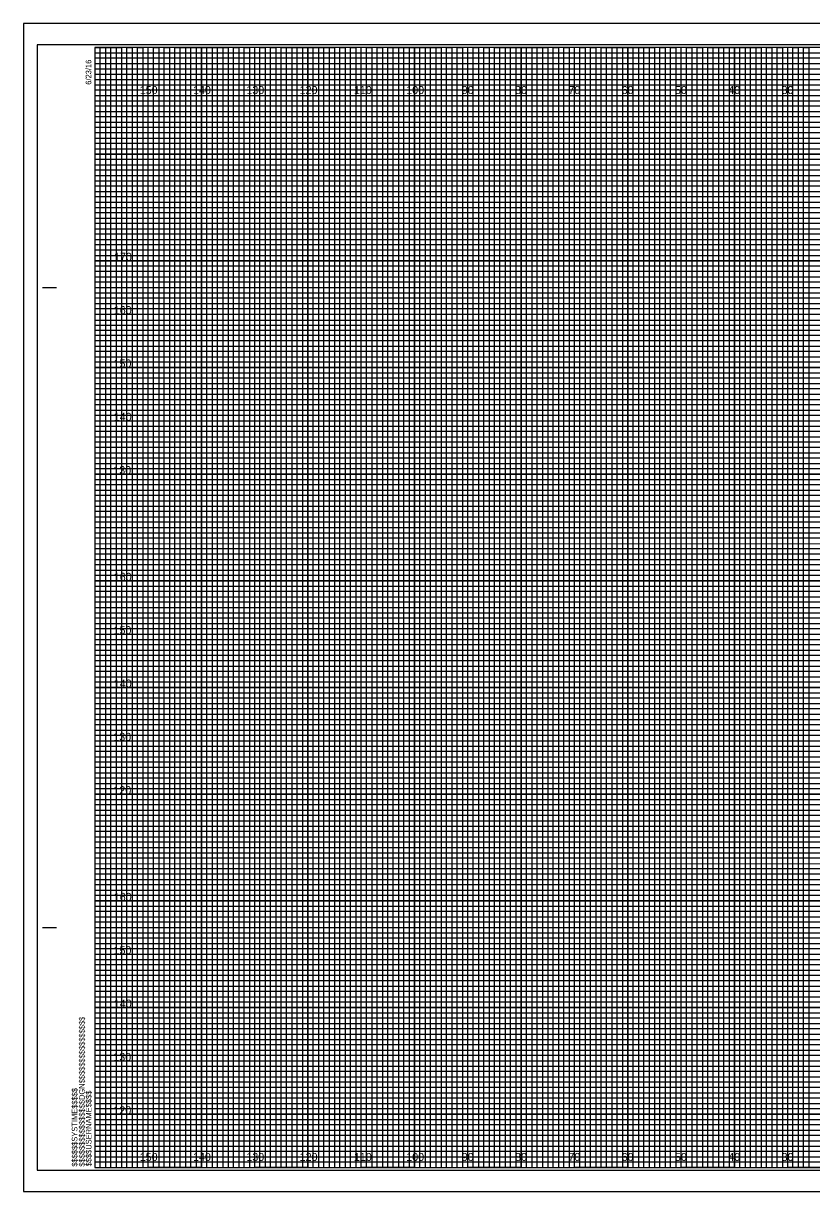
# Model space of a CAD drawing. Extents: x -13 to 323, y -5 to 1094.
# Drawn here: x -13.4 to 134.5, y 875.5 to 1094.5 of the extents above; entities that cross this region are included whole.
import ezdxf

# ---------------------------------------------------------------- set-up
doc = ezdxf.new("R2010")
doc.units = 0
for name, color, linetype in [('Exist Cross Section Cell', 7, 'Continuous'), ('Exist XS Center Line Elevation Label', 7, 'Continuous'), ('Exist XS Ground Line', 7, 'Continuous'), ('Prop CMT Pvmt Course 1', 7, 'Continuous'), ('Prop CMT Pvmt Course 3', 7, 'Continuous'), ('Prop CMT Pvmt Surface', 7, 'Continuous'), ('Prop CMT Pvmt Surface Shoulder', 7, 'Continuous'), ('Prop CMT Shld Paved Course 1', 7, 'Continuous'), ('Prop CMT Shld Paved Course 2', 7, 'Continuous'), ('Prop CMT Shld Paved Course 3', 7, 'Continuous'), ('Prop CMT Subgrade Earthwork', 7, 'Continuous')]:
    doc.layers.add(name, color=color, linetype=linetype)

msp = doc.modelspace()

# ---------------------------------------------------------------- linework, layer by layer
at = {"layer": 'Exist XS Center Line Elevation Label'}
for points in [[(0, 1090), (5, 1090), (5, 880), (15, 880), (15, 1090), (25, 1090), (25, 880), (35, 880), (35, 1090), (45, 1090), (45, 880), (55, 880), (55, 1090), (65, 1090), (65, 880), (75, 880), (75, 1090), (85, 1090), (85, 880), (95, 880), (95, 1090), (105, 1090), (105, 880), (115, 880), (115, 1090), (125, 1090), (125, 880), (135, 880)], [(0, 1085), (275, 1085)], [(0, 1065), (320, 1065), (320, 1075), (0, 1075)], [(0, 1045), (320, 1045), (320, 1055), (0, 1055)], [(0, 1025), (320, 1025), (320, 1035), (0, 1035)], [(0, 1005), (320, 1005), (320, 1015), (0, 1015)], [(0, 985), (320, 985), (320, 995), (0, 995)], [(0, 965), (320, 965), (320, 975), (0, 975)], [(0, 945), (320, 945), (320, 955), (0, 955)], [(0, 925), (320, 925), (320, 935), (0, 935)], [(0, 905), (320, 905), (320, 915), (0, 915)], [(0, 885), (320, 885), (320, 895), (0, 895)]]:
    msp.add_lwpolyline(points, dxfattribs=at)
at = {"layer": 'Exist XS Ground Line'}
for p, q in [((10, 1090), (0, 1090)), ((10, 880), (10, 1090)), ((30, 1090), (20, 1090)), ((20, 1090), (20, 880)), ((30, 880), (30, 1090)), ((50, 1090), (40, 1090)), ((40, 1090), (40, 880)), ((50, 880), (50, 1090)), ((70, 1090), (60, 1090)), ((60, 1090), (60, 880)), ((70, 880), (70, 1090)), ((90, 1090), (80, 1090)), ((80, 1090), (80, 880)), ((90, 880), (90, 1090)), ((110, 1090), (100, 1090)), ((100, 1090), (100, 880)), ((110, 880), (110, 1090)), ((130, 1090), (120, 1090)), ((120, 1090), (120, 880)), ((130, 880), (130, 1090)), ((20, 880), (10, 880)), ((40, 880), (30, 880)), ((60, 880), (50, 880)), ((80, 880), (70, 880)), ((100, 880), (90, 880)), ((120, 880), (110, 880)), ((140, 880), (130, 880))]:
    msp.add_line(p, q, dxfattribs=at)
for points in [[(0, 1080), (320, 1080), (320, 1070), (0, 1070)], [(0, 1060), (320, 1060), (320, 1050), (0, 1050)], [(0, 1040), (320, 1040), (320, 1030), (0, 1030)], [(0, 1020), (320, 1020), (320, 1010), (0, 1010)], [(0, 1000), (320, 1000), (320, 990), (0, 990)], [(0, 980), (320, 980), (320, 970), (0, 970)], [(0, 960), (320, 960), (320, 950), (0, 950)], [(0, 940), (320, 940), (320, 930), (0, 930)], [(0, 920), (320, 920), (320, 910), (0, 910)], [(0, 900), (320, 900), (320, 890), (0, 890)]]:
    msp.add_lwpolyline(points, dxfattribs=at)
at = {"layer": 'Prop CMT Pvmt Course 3'}
msp.add_lwpolyline([(-13.4, 875.5), (323.3, 875.5), (323.3, 1094.5), (-13.4, 1094.5)], close=True, dxfattribs=at)
at = {"layer": 'Prop CMT Pvmt Surface'}
for p, q in [((10, 880), (10, 1090)), ((20, 880), (20, 1090)), ((30, 880), (30, 1090)), ((40, 880), (40, 1090)), ((50, 880), (50, 1090)), ((60, 880), (60, 1090)), ((70, 880), (70, 1090)), ((80, 880), (80, 1090)), ((90, 880), (90, 1090)), ((100, 880), (100, 1090)), ((110, 880), (110, 1090)), ((120, 880), (120, 1090)), ((130, 880), (130, 1090)), ((0, 1080), (320, 1080)), ((0, 1070), (320, 1070)), ((0, 1060), (320, 1060)), ((0, 1050), (320, 1050)), ((0, 1040), (320, 1040)), ((0, 1030), (320, 1030)), ((0, 1020), (320, 1020)), ((0, 1010), (320, 1010)), ((0, 1000), (320, 1000)), ((0, 990), (320, 990)), ((0, 980), (320, 980)), ((0, 970), (320, 970)), ((0, 960), (320, 960)), ((0, 950), (320, 950)), ((0, 940), (320, 940)), ((0, 930), (320, 930)), ((0, 920), (320, 920)), ((0, 910), (320, 910)), ((0, 900), (320, 900)), ((0, 890), (320, 890))]:
    msp.add_line(p, q, dxfattribs=at)
at = {"layer": 'Prop CMT Pvmt Surface Shoulder'}
for p, q in [((323.3, 1094.5), (-13.4, 1094.5)), ((-13.4, 1094.5), (-13.4, 875.5)), ((-13.4, 875.5), (323.3, 875.5))]:
    msp.add_line(p, q, dxfattribs=at)
at = {"layer": 'Prop CMT Shld Paved Course 1'}
for p, q in [((0, 1089), (260, 1089)), ((260, 1087.98), (0, 1087.98)), ((0, 1087.98), (0, 1087)), ((0, 1087), (260, 1087)), ((260, 1085.89), (0, 1085.89)), ((0, 1085.89), (0, 1084)), ((0, 1084), (320, 1084))]:
    msp.add_line(p, q, dxfattribs=at)
for points in [[(0, 1083), (270, 1083), (320, 1083), (320, 1082), (0, 1082)], [(0, 1081), (320, 1081), (320, 1079), (0, 1079)], [(0, 1078), (320, 1078), (320, 1077), (0, 1076.98)], [(0, 1076), (320, 1076), (320, 1074), (0, 1074)], [(0, 1073), (320, 1073), (320, 1072), (0, 1072)], [(0, 1071), (320, 1071), (320, 1069), (0, 1069)], [(0, 1068), (320, 1068), (320, 1067), (0, 1067)], [(0, 1066), (320, 1066), (320, 1064), (0, 1064)], [(0, 1063), (320, 1063), (320, 1062), (0, 1062)], [(0, 1061), (320, 1061), (320, 1059), (0, 1059)], [(0, 1058), (320, 1058), (320, 1057), (0, 1057)], [(0, 1056), (320, 1056), (320, 1053.95), (320, 1053), (320, 1052), (0, 1052)], [(0, 1054), (320, 1054), (320, 1053), (0, 1053)], [(0, 1051), (320, 1051), (320, 1049), (0, 1049.03)], [(0, 1049.03), (320, 1049), (320, 1048), (0, 1048)], [(0, 1047), (320, 1047), (320, 1046), (0, 1046)], [(0, 1044), (320, 1044), (320, 1043), (0, 1043)], [(0, 1042), (320, 1042), (320, 1041), (0, 1041)], [(-0.07, 1038.89), (320, 1038.89), (320, 1037.88), (-0.07, 1037.88)], [(0, 1037), (320, 1037), (320, 1036), (0, 1036)], [(0, 1034), (320, 1034), (320, 1033), (0, 1033)], [(0, 1032), (320, 1032), (320, 1031), (0, 1031)], [(0, 1029), (320, 1029), (320, 1028), (0, 1028)], [(0, 1027), (320, 1027), (320, 1026), (0, 1026)], [(0, 1024), (320, 1024), (320, 1023), (0, 1023)], [(0, 1022), (320, 1022), (320, 1021), (0, 1021)], [(0, 1019), (320, 1019), (319.99, 1017.98), (0, 1018)], [(0, 1017), (320, 1017), (320, 1016), (0, 1016)], [(0, 1014), (320, 1014), (320, 1013), (0, 1013)], [(0, 1012), (320, 1012), (320, 1011), (0, 1011)], [(0, 1009), (320, 1009), (320, 1008), (0, 1008)], [(0, 1007), (320, 1007), (320, 1006), (0, 1006)], [(0, 1004), (320, 1004), (320, 1003), (0, 1003)], [(0, 1002), (320, 1002), (320, 1001), (0, 1001)], [(0, 999), (320, 999), (320, 998), (0, 998)], [(0, 996.99), (320.07, 996.91), (320, 996), (0, 996)], [(0, 994), (320, 994), (320, 993), (0, 993)], [(0, 992), (320, 992), (320, 991), (0, 991)], [(0, 989), (320, 989), (320, 988), (0, 988)], [(0, 987), (320, 987), (320, 986), (0, 986)], [(0, 984), (320, 984), (320, 983), (0, 983)], [(0, 982), (320, 982), (320, 981), (0, 981)], [(0, 979), (320, 979), (320, 978), (0, 978)], [(0, 977), (320, 977), (320, 976), (0, 976)], [(0, 974), (320, 974), (320, 973), (0, 973)], [(0, 972), (320, 972), (320, 971), (0, 971)], [(0, 969), (320, 969), (320, 968), (0, 968)], [(0, 967), (320, 967), (320, 966), (0, 966)], [(0, 964), (320, 964), (320, 963), (0, 963)], [(0, 962), (320, 962), (320, 961), (0, 961)], [(0, 959), (320, 959), (319.99, 957.98), (0, 958)], [(0, 957), (320, 957), (320, 956), (0, 956)], [(0, 954), (320, 954), (320, 953), (0, 953)], [(0, 952), (320, 952), (320, 951), (0, 951)], [(0, 949), (320, 949), (320, 948), (0, 948)], [(0, 947), (320, 947), (320, 946), (0, 946)], [(0, 944), (320, 944), (320, 943), (0, 943)], [(0, 942), (320, 942), (320, 941), (0, 941)], [(0, 939), (320, 939), (320, 938), (0, 938)], [(0, 936.99), (320.07, 936.91), (320, 936), (0, 936)], [(0, 934), (320, 934), (320, 933), (0, 933)], [(0, 932), (320, 932), (320, 931), (0, 931)], [(0, 929), (320, 929), (320, 928), (0, 928)], [(0, 927), (320, 927), (320, 926), (0, 926)], [(0, 924), (320, 924), (320, 923), (0, 923)], [(0, 922), (320, 922), (320, 921), (0, 921)], [(0, 919), (320, 919), (320, 918), (0, 918)], [(0, 917), (320, 917), (320, 916), (0, 916)], [(0, 914), (320, 914), (320, 913), (0, 913)], [(0, 912), (320, 912), (320, 911), (0, 911)], [(0, 909), (320, 909), (320, 908), (0, 908)], [(0, 907), (320, 907), (320, 906), (0, 906)], [(0, 904), (320, 904), (320, 903), (0, 903)], [(0, 902), (320, 902), (320, 901), (0, 901)], [(0, 899), (320, 899), (320, 898), (0, 898)], [(0, 897), (320, 897), (320, 896), (0, 896)], [(0, 894), (320, 894), (320, 893), (0, 893)], [(0, 892), (320, 892), (320, 891), (0, 891)], [(0, 889), (320, 889), (320, 888), (0, 888)], [(0, 887), (320, 887), (320, 886), (0, 886)], [(0, 884), (320, 884), (320, 883), (0, 883)], [(0, 882), (320, 882), (320, 881), (0, 881)]]:
    msp.add_lwpolyline(points, dxfattribs=at)
at = {"layer": 'Prop CMT Shld Paved Course 2'}
for p, q in [((-9.8, 1045), (-7.3, 1045)), ((-9.7, 1045), (-7.2, 1045)), ((-9.8, 925), (-7.3, 925)), ((-9.7, 925), (-7.2, 925)), ((0, 880), (0, 880)), ((0, 880), (0, 880)), ((0, 880), (0, 880)), ((0, 880), (0, 880)), ((0, 880), (0, 880)), ((0, 880), (0, 880)), ((0, 880), (0, 880))]:
    msp.add_line(p, q, dxfattribs=at)
msp.add_lwpolyline([(320, 1090), (0, 1090), (0, 880), (320, 880)], close=True, dxfattribs=at)
at = {"layer": 'Prop CMT Shld Paved Course 3'}
for points in [[(0, 880), (1, 880), (1, 1090), (2, 1090), (2, 880)], [(2, 880), (3, 880), (3, 1090), (4, 1090), (4, 880)], [(5, 880), (6, 880), (6, 1090), (7, 1090), (7, 880)], [(7, 880), (8, 880), (8, 1090), (9, 1090), (9, 880)], [(10, 880), (11, 880), (11, 1090), (12, 1090), (12, 880)], [(12, 880), (13, 880), (13, 1090), (14, 1090), (14, 880)], [(15, 880), (16, 880), (16, 1090), (17, 1090), (17, 880)], [(17, 880), (18, 880), (18, 1090), (19, 1090), (19, 880)], [(20, 880), (21, 880), (21, 1090), (22, 1090), (22, 880)], [(22, 880), (23, 880), (23, 1090), (24, 1090), (24, 880)], [(25, 880), (26, 880), (26, 1090), (27, 1090), (27, 880)], [(27, 880), (28, 880), (28, 1090), (29, 1090), (29, 880)], [(30, 880), (31, 880), (31, 1090), (32, 1090), (32, 880)], [(32, 880), (33, 880), (33, 1090), (34, 1090), (34, 880)], [(35, 880), (36, 880), (36, 1090), (37, 1090), (37, 880)], [(37, 880), (38, 880), (38, 1090), (39, 1090), (39, 880)], [(40, 880), (41, 880), (41, 1090), (42, 1090), (42, 880)], [(42, 880), (43, 880), (43, 1090), (44, 1090), (44, 880)], [(45, 880), (46, 880), (46, 1090), (47, 1090), (47, 880)], [(47, 880), (48, 880), (48, 1090), (49, 1090), (49, 880)], [(50, 880), (51, 880), (51, 1090), (52, 1090), (52, 880)], [(52, 880), (53, 880), (53, 1090), (54, 1090), (54, 880)], [(55, 880), (56, 880), (56, 1090), (57, 1090), (57, 880)], [(57, 880), (58, 880), (58, 1090), (59, 1090), (59, 880)], [(60, 880), (61, 880), (61, 1090), (62, 1090), (62, 880)], [(62, 880), (63, 880), (63, 1090), (64, 1090), (64, 880)], [(65, 880), (66, 880), (66, 1090), (67, 1090), (67, 880)], [(67, 880), (68, 880), (68, 1090), (69, 1090), (69, 880)], [(70, 880), (71, 880), (71, 1090), (72, 1090), (72, 880)], [(72, 880), (73, 880), (73, 1090), (74, 1090), (74, 880)], [(75, 880), (76, 880), (76, 1090), (77, 1090), (77, 880)], [(77, 880), (78, 880), (78, 1090), (79, 1090), (79, 880)], [(80, 880), (81, 880), (81, 1090), (82, 1090), (82, 880)], [(82, 880), (83, 880), (83, 1090), (84, 1090), (84, 880)], [(85, 880), (86, 880), (86, 1090), (87, 1090), (87, 880)], [(87, 880), (88, 880), (88, 1090), (89, 1090), (89, 880)], [(90, 880), (91, 880), (91, 1090), (92, 1090), (92, 880)], [(92, 880), (93, 880), (93, 1090), (94, 1090), (94, 880)], [(95, 880), (96, 880), (96, 1090), (97, 1090), (97, 880)], [(97, 880), (98, 880), (98, 1090), (99, 1090), (99, 880)], [(100, 880), (101, 880), (101, 1090), (102, 1090), (102, 880)], [(102, 880), (103, 880), (103, 1090), (104, 1090), (104, 880)], [(105, 880), (106, 880), (106, 1090), (107, 1090), (107, 880)], [(107, 880), (108, 880), (108, 1090), (109, 1090), (109, 880)], [(110, 880), (111, 880), (111, 1090), (112, 1090), (112, 880)], [(112, 880), (113, 880), (113, 1090), (114, 1090), (114, 880)], [(115, 880), (116, 880), (116, 1090), (117, 1090), (117, 880)], [(117, 880), (118, 880), (118, 1090), (119, 1090), (119, 880)], [(120, 880), (121, 880), (121, 1090), (122, 1090), (122, 880)], [(122, 880), (123, 880), (123, 1090), (124, 1090), (124, 880)], [(125, 880), (126, 880), (126, 1090), (127, 1090), (127, 880)], [(127, 880), (128, 880), (128, 1090), (129, 1090), (129, 880)], [(130, 880), (131, 880), (131, 1090), (132, 1090), (132, 880)], [(132, 880), (133, 880), (133, 1090), (134, 1090), (134, 880)]]:
    msp.add_lwpolyline(points, dxfattribs=at)
at = {"layer": 'Prop CMT Subgrade Earthwork'}
msp.add_lwpolyline([(-10.8, 879.5), (322.4, 879.5), (322.4, 1090.5), (-10.8, 1090.5)], close=True, dxfattribs=at)

# ---------------------------------------------------------------- texts
at = {"layer": 'Exist Cross Section Cell'}
for s, p in [('150', (8.44, 1081.25)), ('140', (18.44, 1081.25)), ('130', (28.44, 1081.25)), ('120', (38.44, 1081.25)), ('110', (48.62, 1081.25)), ('100', (58.44, 1081.25)), ('90', (68.86, 1081.25)), ('80', (78.86, 1081.25)), ('70', (88.86, 1081.25)), ('60', (98.86, 1081.25)), ('50', (108.86, 1081.25)), ('40', (118.86, 1081.25)), ('30', (128.86, 1081.25)), ('150', (8.44, 881.25)), ('140', (18.44, 881.25)), ('130', (28.44, 881.25)), ('120', (38.44, 881.25)), ('110', (48.62, 881.25)), ('100', (58.44, 881.25)), ('90', (68.86, 881.25)), ('80', (78.86, 881.25)), ('70', (88.86, 881.25)), ('60', (98.86, 881.25)), ('50', (108.86, 881.25)), ('40', (118.86, 881.25)), ('30', (128.86, 881.25))]:
    msp.add_text(s, height=1.5, dxfattribs=at).set_placement(p)
at = {"layer": 'Prop CMT Pvmt Course 1'}
for s, p in [('170', (3.61, 1050)), ('160', (3.57, 1040)), ('150', (3.52, 1030)), ('140', (3.57, 1020)), ('130', (3.49, 1010)), ('160', (3.57, 990)), ('150', (3.52, 980)), ('140', (3.57, 970)), ('130', (3.49, 960)), ('120', (3.5, 950)), ('160', (3.57, 930)), ('150', (3.52, 920)), ('140', (3.57, 910)), ('130', (3.49, 900)), ('120', (3.5, 890))]:
    msp.add_text(s, height=1.5, dxfattribs=at).set_placement(p)
at = {"layer": 'Prop CMT Shld Paved Course 2'}
for s, p in [('6/23/16', (-0.65, 1083)), ('$$$$$$$$$$$$$$$$DGN$$$$$$$$$$$$$$$$', (-1.88, 880.18)), ('$$$$$$SYSTIME$$$$$', (-3.26, 880.18)), ('$$$$USERNAME$$$$', (-0.62, 880.23))]:
    msp.add_text(s, height=1.05, rotation=90, dxfattribs=at).set_placement(p)

doc.saveas('drawing.dxf')
